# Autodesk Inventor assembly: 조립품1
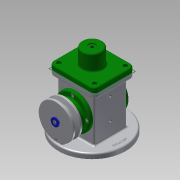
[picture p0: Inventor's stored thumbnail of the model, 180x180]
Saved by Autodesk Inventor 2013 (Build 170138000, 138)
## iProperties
Created: 2019-08
Part Number: 조립품1
Document SubType Name: Assembly
Designer: Administrator
Author: Administrator
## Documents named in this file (18)
- C:\Users\Administrator\Desktop\490804V1037\조립품1.iam
- C:\Users\Administrator\Desktop\490804V1037\본체1.ipt
- C:\Users\Administrator\Desktop\490804V1037\E-링.ipt
- C:\Users\Administrator\Desktop\490804V1037\V-벨트풀리 - 복사본.ipt
- C:\Users\Administrator\Desktop\490804V1037\덮개 - 복사본.ipt
- C:\Users\Administrator\Desktop\490804V1037\뒤커버.ipt
- C:\Users\Administrator\Desktop\490804V1037\링크.ipt
- C:\Users\Administrator\Desktop\490804V1037\베어링 17 x 40 x 12.ipt
- C:\Users\Administrator\Desktop\490804V1037\볼트 M4 x 8.ipt
- C:\Users\Administrator\Desktop\490804V1037\볼트 M4 x 10.ipt
- C:\Users\Administrator\Desktop\490804V1037\슬라이더.ipt
- C:\Users\Administrator\Desktop\490804V1037\앞커버.ipt
- C:\Users\Administrator\Desktop\490804V1037\오일 실 17 30 8.ipt
- C:\Users\Administrator\Desktop\490804V1037\와셔 4x16.ipt
- C:\Users\Administrator\Desktop\490804V1037\클레비스 핀 6 x 22.ipt
- 클레비스 핀 6 x 22.ipt
- C:\Users\Administrator\Desktop\490804V1037\키 4 x 4 x 12.ipt
- C:\Users\Administrator\Desktop\490804V1037\편심축.ipt
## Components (2 placed, 2 different names)
1. E-링:1
2. V-벨트풀리 - 복사본:1
